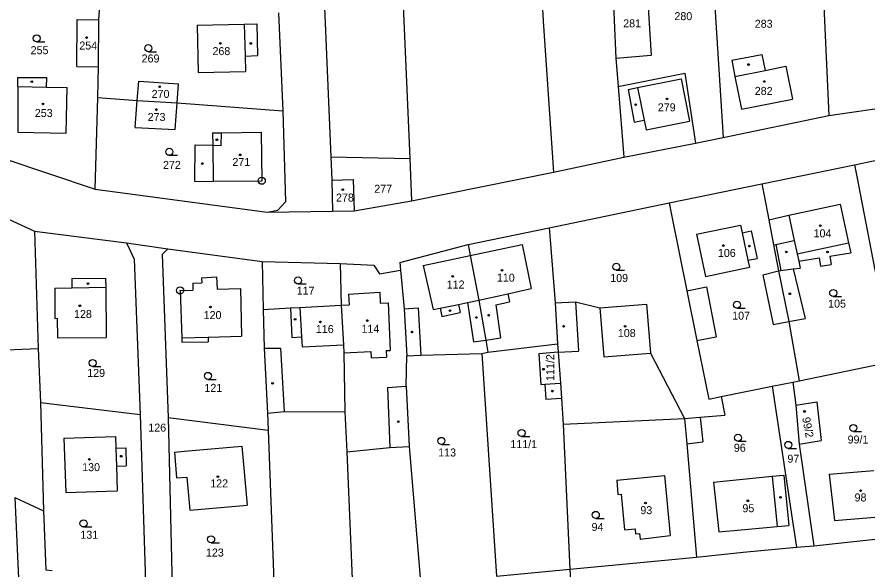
# Model space of a CAD drawing. Extents: x -779596 to -776743, y -1030330 to -1024513.
# Drawn here: x -778366.4 to -778185.6, y -1024921.7 to -1024804.1 of the extents above; entities that cross this region are included whole.
import ezdxf

# ---------------------------------------------------------------- set-up
doc = ezdxf.new("R2010")
doc.units = 0
for name, color, linetype in [('hranice parcel', 7, 'Continuous'), ('hranice vnitřní', 7, 'Continuous'), ('kultura', 7, 'Continuous'), ('Kód', 7, 'Continuous'), ('č_pacel stav_', 7, 'Continuous'), ('č_parcel poz_', 7, 'Continuous')]:
    doc.layers.add(name, color=color, linetype=linetype)

msp = doc.modelspace()

# ---------------------------------------------------------------- linework, layer by layer
at = {"layer": 'hranice parcel'}
for points in [[(-778256.34, -1024772.55), (-778254.57, -1024805)], [(-778301.94, -1024780.27), (-778299.71, -1024833.83)], [(-778218.94, -1024788.46), (-778216.34, -1024829.72)], [(-778195.58, -1024787.78), (-778193.9, -1024825.06)], [(-778232.64, -1024796.31), (-778231.66, -1024812.23)], [(-778239.85, -1024796.61), (-778239.11, -1024812.84)], [(-778348.96, -1024804.66), (-778348.79, -1024801.64)], [(-778284.34, -1024801.62), (-778282.93, -1024834.15)], [(-778310.82, -1024803.21), (-778309.88, -1024824.04)], [(-778353.64, -1024814.62), (-778353.56, -1024804.62)], [(-778353.56, -1024804.62), (-778348.96, -1024804.66)], [(-778349.04, -1024814.66), (-778348.96, -1024804.66)], [(-778318.07, -1024805.6), (-778315.4, -1024805.53)], [(-778315.4, -1024805.53), (-778315.24, -1024812.3)], [(-778254.57, -1024805), (-778252.38, -1024837.07)], [(-778328.08, -1024805.83), (-778318.07, -1024805.6)], [(-778328.08, -1024805.83), (-778327.84, -1024815.89)], [(-778317.91, -1024812.38), (-778315.24, -1024812.3)], [(-778317.91, -1024812.38), (-778317.83, -1024815.66)], [(-778239.11, -1024812.84), (-778231.66, -1024812.23)], [(-778214.51, -1024813.26), (-778208.08, -1024812.08)], [(-778208.08, -1024812.08), (-778207.42, -1024815.44)], [(-778239.11, -1024812.84), (-778238.64, -1024818.89)], [(-778214.51, -1024813.26), (-778213.83, -1024816.71)], [(-778207.42, -1024815.44), (-778203, -1024814.57)], [(-778203, -1024814.57), (-778201.62, -1024821.54)], [(-778353.64, -1024814.62), (-778349.04, -1024814.66)], [(-778349.21, -1024821.2), (-778349.04, -1024814.66)], [(-778327.84, -1024815.89), (-778317.83, -1024815.66)], [(-778238.64, -1024818.89), (-778224.49, -1024816.06)], [(-778224.49, -1024816.06), (-778222.21, -1024830.88)], [(-778366.2, -1024816.96), (-778360.04, -1024816.97)], [(-778366.2, -1024818.85), (-778366.2, -1024816.96)], [(-778360.08, -1024818.97), (-778360.04, -1024816.97)], [(-778340.81, -1024821.87), (-778340.49, -1024817.73)], [(-778340.49, -1024817.73), (-778332.08, -1024818.33)], [(-778213.83, -1024816.71), (-778212.45, -1024823.68)], [(-778366.2, -1024818.85), (-778366.18, -1024828.6)], [(-778360.08, -1024818.97), (-778355.73, -1024819.06)], [(-778355.92, -1024828.8), (-778355.73, -1024819.06)], [(-778332.33, -1024822.31), (-778332.08, -1024818.33)], [(-778238.64, -1024818.89), (-778237.46, -1024833.89)], [(-778349.75, -1024840.68), (-778349.21, -1024821.2)], [(-778349.21, -1024821.2), (-778340.81, -1024821.87)], [(-778212.45, -1024823.68), (-778201.62, -1024821.54)], [(-778341.28, -1024827.57), (-778340.81, -1024821.87)], [(-778340.81, -1024821.87), (-778332.33, -1024822.31)], [(-778332.78, -1024828), (-778332.33, -1024822.31)], [(-778332.33, -1024822.31), (-778309.88, -1024824.04)], [(-778193.9, -1024825.06), (-778184.1, -1024823.61)], [(-778309.88, -1024824.04), (-778309.34, -1024843.4)], [(-778216.34, -1024829.72), (-778193.9, -1024825.06)], [(-778366.18, -1024828.6), (-778355.92, -1024828.8)], [(-778341.28, -1024827.57), (-778332.78, -1024828)], [(-778324.8, -1024828.71), (-778322.91, -1024828.69)], [(-778324.8, -1024828.71), (-778324.77, -1024831.35)], [(-778322.91, -1024828.69), (-778314.47, -1024828.6)], [(-778314.47, -1024828.6), (-778314.37, -1024838.91)], [(-778222.21, -1024830.88), (-778216.34, -1024829.72)], [(-778328.6, -1024839.03), (-778328.49, -1024831.24)], [(-778328.49, -1024831.24), (-778324.77, -1024831.35)], [(-778237.46, -1024833.89), (-778222.21, -1024830.88)], [(-778188.42, -1024835.49), (-778173.59, -1024832.42)], [(-778369.19, -1024834.14), (-778349.75, -1024840.68)], [(-778299.71, -1024833.83), (-778282.93, -1024834.15)], [(-778299.71, -1024833.83), (-778299.46, -1024838.75)], [(-778282.93, -1024834.15), (-778282.54, -1024843.14)], [(-778252.38, -1024837.07), (-778237.46, -1024833.89)], [(-778208.13, -1024839.56), (-778188.42, -1024835.49)], [(-778188.42, -1024835.49), (-778187.93, -1024838.01)], [(-778282.54, -1024843.14), (-778252.38, -1024837.07)], [(-778187.93, -1024838.01), (-778180.36, -1024877.36)], [(-778328.6, -1024839.03), (-778324.69, -1024839)], [(-778324.69, -1024839), (-778314.37, -1024838.91)], [(-778299.46, -1024838.75), (-778294.92, -1024838.64)], [(-778299.46, -1024838.75), (-778299.31, -1024845.38)], [(-778294.92, -1024838.64), (-778294.76, -1024845.28)], [(-778227.83, -1024843.63), (-778208.13, -1024839.56)], [(-778208.13, -1024839.56), (-778207.65, -1024842.05)], [(-778380.51, -1024841.39), (-778362.66, -1024849.65)], [(-778349.75, -1024840.68), (-778313.18, -1024845.6)], [(-778310.98, -1024845.12), (-778309.34, -1024843.4)], [(-778294.76, -1024845.28), (-778282.54, -1024843.14)], [(-778207.65, -1024842.05), (-778206.66, -1024847.18)], [(-778313.18, -1024845.6), (-778310.98, -1024845.12)], [(-778299.31, -1024845.38), (-778294.76, -1024845.28)], [(-778253.29, -1024848.88), (-778227.83, -1024843.63)], [(-778227.83, -1024843.63), (-778227.32, -1024846.16)], [(-778202.36, -1024846.25), (-778191.48, -1024843.89)], [(-778191.48, -1024843.89), (-778189.67, -1024852.09)], [(-778313.18, -1024845.6), (-778299.31, -1024845.38)], [(-778227.32, -1024846.16), (-778224.02, -1024862.29)], [(-778206.66, -1024847.18), (-778202.36, -1024846.25)], [(-778270.52, -1024852.44), (-778253.29, -1024848.88)], [(-778253.29, -1024848.88), (-778253.08, -1024851.45)], [(-778221.99, -1024850.28), (-778212.66, -1024848.32)], [(-778212.66, -1024848.32), (-778212.31, -1024849.95)], [(-778206.66, -1024847.18), (-778205.62, -1024852.53)], [(-778362.66, -1024849.65), (-778343.1, -1024852.11)], [(-778362.66, -1024849.65), (-778361.84, -1024874.54)], [(-778221.99, -1024850.28), (-778220.1, -1024859.27)], [(-778212.31, -1024849.95), (-778210.36, -1024849.54)], [(-778210.36, -1024849.54), (-778209.12, -1024855.4)], [(-778343.1, -1024852.11), (-778334.33, -1024853.38)], [(-778343.1, -1024852.11), (-778341.49, -1024855.59)], [(-778285.04, -1024856.31), (-778270.52, -1024852.44)], [(-778270.52, -1024852.44), (-778270.06, -1024854.8)], [(-778253.08, -1024851.45), (-778252.01, -1024864.87)], [(-778205.62, -1024852.53), (-778204.55, -1024858.06)], [(-778189.67, -1024852.09), (-778189.2, -1024854.2)], [(-778335.53, -1024854.58), (-778334.33, -1024853.38)], [(-778334.33, -1024853.38), (-778314.27, -1024856.1)], [(-778193.64, -1024854.94), (-778189.2, -1024854.2)], [(-778341.49, -1024855.59), (-778340.22, -1024888.58)], [(-778335.53, -1024854.58), (-778334.26, -1024889.22)], [(-778314.27, -1024856.1), (-778314.05, -1024866.26)], [(-778314.27, -1024856.1), (-778297.73, -1024856.46)], [(-778270.06, -1024854.8), (-778268.22, -1024864.3)], [(-778211.06, -1024855.81), (-778209.12, -1024855.4)], [(-778211.06, -1024855.81), (-778210.75, -1024857.3)], [(-778200.25, -1024856.03), (-778195.92, -1024855.31)], [(-778200.25, -1024856.03), (-778199.94, -1024857.46)], [(-778195.92, -1024855.31), (-778195.63, -1024857.07)], [(-778193.64, -1024854.94), (-778193.36, -1024856.69)], [(-778297.73, -1024856.46), (-778290.52, -1024856.86)], [(-778297.73, -1024856.46), (-778297.46, -1024865.37)], [(-778290.52, -1024856.86), (-778289.36, -1024858.7)], [(-778289.36, -1024858.7), (-778284.92, -1024857.9)], [(-778285.04, -1024856.31), (-778284.92, -1024857.9)], [(-778284.92, -1024857.9), (-778284.11, -1024866.13)], [(-778220.1, -1024859.27), (-778210.75, -1024857.3)], [(-778201.49, -1024857.66), (-778199.94, -1024857.46)], [(-778201.49, -1024857.66), (-778198.91, -1024868.18)], [(-778195.63, -1024857.07), (-778193.36, -1024856.69)], [(-778354.73, -1024859.68), (-778347.53, -1024859.61)], [(-778354.73, -1024859.68), (-778354.71, -1024861.69)], [(-778347.53, -1024859.61), (-778347.51, -1024861.55)], [(-778327.16, -1024859.53), (-778323.95, -1024859.36)], [(-778327.16, -1024859.53), (-778327.13, -1024860.6)], [(-778323.95, -1024859.36), (-778323.87, -1024861.97)], [(-778204.55, -1024858.06), (-778202.35, -1024868.81)], [(-778347.51, -1024861.55), (-778347.4, -1024872.19)], [(-778329.04, -1024860.66), (-778327.13, -1024860.6)], [(-778329.04, -1024860.66), (-778328.99, -1024862.13)], [(-778358.36, -1024861.73), (-778354.71, -1024861.69)], [(-778358.36, -1024861.73), (-778358.3, -1024868.15)], [(-778331.7, -1024862.22), (-778328.99, -1024862.13)], [(-778331.7, -1024862.22), (-778331.37, -1024872.27)], [(-778323.87, -1024861.97), (-778318.91, -1024861.81)], [(-778318.91, -1024861.81), (-778318.65, -1024871.95)], [(-778224.02, -1024862.29), (-778221.95, -1024872.89)], [(-778268.22, -1024864.3), (-778266.77, -1024872.76)], [(-778252.01, -1024864.87), (-778247.73, -1024864.61)], [(-778252.01, -1024864.87), (-778251.53, -1024873.56)], [(-778247.73, -1024864.61), (-778242.56, -1024865.95)], [(-778242.56, -1024865.95), (-778232.63, -1024865.14)], [(-778232.63, -1024865.14), (-778231.78, -1024875.52)], [(-778314.05, -1024866.26), (-778308.29, -1024865.95)], [(-778314.05, -1024866.26), (-778313.87, -1024874.52)], [(-778308.29, -1024865.95), (-778306.24, -1024865.84)], [(-778306.24, -1024865.84), (-778297.46, -1024865.37)], [(-778297.46, -1024865.37), (-778297.01, -1024873.76)], [(-778284.11, -1024866.13), (-778283.54, -1024876.13)], [(-778358.3, -1024868.15), (-778357.83, -1024868.14)], [(-778357.83, -1024868.14), (-778357.78, -1024872.3)], [(-778202.35, -1024868.81), (-778198.91, -1024868.18)], [(-778202.35, -1024868.81), (-778200.17, -1024881.44)], [(-778357.78, -1024872.3), (-778347.4, -1024872.19)], [(-778331.37, -1024872.27), (-778331.35, -1024873.21)], [(-778325.77, -1024872.13), (-778318.65, -1024871.95)], [(-778325.77, -1024872.13), (-778325.75, -1024873.13)], [(-778331.35, -1024873.21), (-778325.75, -1024873.13)], [(-778297.01, -1024873.76), (-778296.92, -1024875.45)], [(-778266.77, -1024872.76), (-778266.32, -1024875.36)], [(-778266.32, -1024875.36), (-778251.53, -1024873.56)], [(-778251.53, -1024873.56), (-778251.36, -1024875.37)], [(-778221.95, -1024872.89), (-778219.39, -1024885.31)], [(-778382.36, -1024875.42), (-778361.84, -1024874.54)], [(-778361.84, -1024874.54), (-778361.4, -1024886.04)], [(-778313.87, -1024874.52), (-778313.13, -1024888.28)], [(-778296.92, -1024875.45), (-778296.68, -1024888.03)], [(-778283.54, -1024876.13), (-778280.56, -1024875.95)], [(-778280.56, -1024875.95), (-778267.62, -1024875.64)], [(-778267.62, -1024875.64), (-778266.32, -1024875.36)], [(-778267.62, -1024875.64), (-778264.46, -1024922.95)], [(-778251.36, -1024875.37), (-778255.52, -1024875.69), (-778255.1, -1024882.24), (-778254.2, -1024882.18)], [(-778251.36, -1024875.37), (-778250.91, -1024881.94)], [(-778231.78, -1024875.52), (-778224.52, -1024889.41)], [(-778283.65, -1024882.57), (-778283.54, -1024876.13)], [(-778200.17, -1024881.44), (-778180.36, -1024877.36)], [(-778201.55, -1024881.73), (-778200.17, -1024881.44)], [(-778283.65, -1024882.57), (-778283.04, -1024895.41)], [(-778254.2, -1024882.18), (-778253.99, -1024885.35), (-778250.7, -1024885.11)], [(-778250.91, -1024881.94), (-778250.7, -1024885.11)], [(-778216.75, -1024884.78), (-778205.89, -1024882.6)], [(-778205.89, -1024882.6), (-778201.55, -1024881.73)], [(-778205.89, -1024882.6), (-778201.45, -1024912.17)], [(-778201.55, -1024881.73), (-778200.92, -1024886.61)], [(-778219.39, -1024885.31), (-778216.75, -1024884.78)], [(-778216.75, -1024884.78), (-778215.95, -1024888.76)], [(-778361.4, -1024886.04), (-778360.72, -1024909.04)], [(-778361.4, -1024886.04), (-778340.22, -1024888.58)], [(-778250.7, -1024885.11), (-778250.32, -1024890.66)], [(-778200.92, -1024886.61), (-778196.42, -1024885.87)], [(-778200.92, -1024886.61), (-778200.15, -1024894.89)], [(-778196.42, -1024885.87), (-778195.49, -1024894.14)], [(-778340.22, -1024888.58), (-778339.08, -1024924.32)], [(-778313.13, -1024888.28), (-778309.63, -1024887.94)], [(-778313.13, -1024888.28), (-778312.99, -1024891.95)], [(-778309.63, -1024887.94), (-778296.68, -1024888.03)], [(-778296.68, -1024888.03), (-778296.32, -1024896.54)], [(-778334.26, -1024889.22), (-778333.42, -1024925.33)], [(-778334.26, -1024889.22), (-778312.99, -1024891.95)], [(-778250.32, -1024890.66), (-778224.52, -1024889.41)], [(-778224.52, -1024889.41), (-778221.19, -1024889.16)], [(-778224.52, -1024889.41), (-778224.05, -1024894.82)], [(-778221.19, -1024889.16), (-778215.95, -1024888.76)], [(-778312.99, -1024891.95), (-778311.64, -1024927.84)], [(-778250.32, -1024890.66), (-778248.92, -1024921.44)], [(-778356.4, -1024893.65), (-778345.45, -1024893.28)], [(-778356.4, -1024893.65), (-778356.01, -1024905.17)], [(-778345.45, -1024893.28), (-778345.37, -1024895.77)], [(-778345.37, -1024895.77), (-778343.27, -1024895.69)], [(-778343.27, -1024895.69), (-778343.14, -1024899.5)], [(-778330.76, -1024896.4), (-778318.59, -1024895.3)], [(-778318.59, -1024895.3), (-778317.47, -1024907.85)], [(-778296.32, -1024896.54), (-778287.13, -1024895.63)], [(-778287.13, -1024895.63), (-778283.04, -1024895.41)], [(-778283.04, -1024895.41), (-778278.99, -1024943.52)], [(-778224.05, -1024894.82), (-778221.99, -1024918.91)], [(-778200.15, -1024894.89), (-778195.49, -1024894.14)], [(-778200.15, -1024894.89), (-778197.06, -1024916.48)], [(-778332.9, -1024896.59), (-778330.76, -1024896.4)], [(-778332.9, -1024896.59), (-778332.47, -1024902.09)], [(-778296.32, -1024896.54), (-778294.27, -1024943.79)], [(-778345.24, -1024899.57), (-778343.14, -1024899.5)], [(-778345.24, -1024899.57), (-778345.07, -1024904.8)], [(-778193.8, -1024901.26), (-778184.29, -1024900.49)], [(-778193.8, -1024901.26), (-778192.67, -1024911.14)], [(-778332.47, -1024902.09), (-778330.26, -1024901.9)], [(-778330.26, -1024901.9), (-778329.63, -1024908.95)], [(-778238.94, -1024902.55), (-778228.82, -1024901.59)], [(-778238.94, -1024902.55), (-778238.7, -1024905.6)], [(-778228.82, -1024901.59), (-778227.62, -1024914.32)], [(-778218.38, -1024902.95), (-778205.9, -1024901.73)], [(-778218.38, -1024902.95), (-778217.25, -1024913.55)], [(-778205.9, -1024901.73), (-778203.42, -1024901.49)], [(-778203.42, -1024901.49), (-778202.4, -1024912.18)], [(-778356.01, -1024905.17), (-778345.07, -1024904.8)], [(-778366.82, -1024906.22), (-778360.72, -1024909.04)], [(-778366.82, -1024906.22), (-778364.24, -1024963.97)], [(-778238.7, -1024905.6), (-778237.97, -1024905.56)], [(-778237.97, -1024905.56), (-778237.26, -1024913.1)], [(-778329.63, -1024908.95), (-778317.47, -1024907.85)], [(-778360.72, -1024909.04), (-778360.27, -1024921.6)], [(-778192.67, -1024911.14), (-778180.62, -1024910.17)], [(-778204.85, -1024912.41), (-778202.4, -1024912.18)], [(-778201.45, -1024912.17), (-778200.75, -1024916.82)], [(-778237.26, -1024913.1), (-778235.06, -1024912.88)], [(-778235.06, -1024912.88), (-778234.96, -1024913.93)], [(-778234.96, -1024913.93), (-778234.08, -1024913.87)], [(-778234.08, -1024913.87), (-778233.97, -1024915.08)], [(-778217.25, -1024913.55), (-778212.49, -1024913.11)], [(-778212.49, -1024913.11), (-778204.85, -1024912.41)], [(-778233.97, -1024915.08), (-778227.62, -1024914.32)], [(-778197.06, -1024916.48), (-778174.88, -1024914.1)], [(-778212.09, -1024917.86), (-778200.75, -1024916.82)], [(-778200.75, -1024916.82), (-778197.06, -1024916.48)], [(-778248.92, -1024921.44), (-778221.99, -1024918.91)], [(-778221.99, -1024918.91), (-778216.74, -1024918.35)], [(-778216.74, -1024918.35), (-778212.09, -1024917.86)], [(-778360.27, -1024921.6), (-778358.88, -1024921.78)], [(-778264.46, -1024922.95), (-778248.92, -1024921.44)], [(-778248.92, -1024921.44), (-778248.34, -1024931.1)]]:
    msp.add_lwpolyline(points, dxfattribs=at)
at = {"layer": 'hranice vnitřní'}
for points in [[(-778318.07, -1024805.6), (-778317.91, -1024812.38)], [(-778213.83, -1024816.71), (-778207.42, -1024815.44)], [(-778234.51, -1024819.08), (-778225.27, -1024817.23)], [(-778225.27, -1024817.23), (-778223.47, -1024826.2)], [(-778366.2, -1024818.85), (-778360.08, -1024818.97)], [(-778236.53, -1024819.48), (-778234.51, -1024819.08)], [(-778236.53, -1024819.48), (-778235.27, -1024826.46)], [(-778234.51, -1024819.08), (-778233.12, -1024826.03)], [(-778235.27, -1024826.46), (-778233.12, -1024826.03)], [(-778233.12, -1024826.03), (-778232.71, -1024828.05)], [(-778232.71, -1024828.05), (-778223.47, -1024826.2)], [(-778322.98, -1024831.4), (-778322.91, -1024828.69)], [(-778324.77, -1024831.35), (-778322.98, -1024831.4)], [(-778324.77, -1024831.35), (-778324.69, -1024839)], [(-778202.36, -1024846.25), (-778201.21, -1024851.58)], [(-778212.31, -1024849.95), (-778211.06, -1024855.81)], [(-778270.06, -1024854.8), (-778259.05, -1024852.48)], [(-778259.05, -1024852.48), (-778257.09, -1024861.82)], [(-778205.62, -1024852.53), (-778205.12, -1024852.42)], [(-778205.12, -1024852.42), (-778201.21, -1024851.58)], [(-778205.12, -1024852.42), (-778204.05, -1024858)], [(-778201.21, -1024851.58), (-778200.59, -1024854.46)], [(-778200.59, -1024854.46), (-778189.67, -1024852.09)], [(-778280.09, -1024856.9), (-778270.06, -1024854.8)], [(-778200.59, -1024854.46), (-778200.25, -1024856.03)], [(-778280.09, -1024856.9), (-778277.93, -1024866.28)], [(-778204.05, -1024858), (-778201.49, -1024857.66)], [(-778207.89, -1024858.91), (-778204.55, -1024858.06)], [(-778207.89, -1024858.91), (-778205.71, -1024869.43)], [(-778204.55, -1024858.06), (-778204.05, -1024858)], [(-778354.71, -1024861.69), (-778347.51, -1024861.55)], [(-778224.02, -1024862.29), (-778219.9, -1024861.48)], [(-778219.9, -1024861.48), (-778217.83, -1024872.08)], [(-778295.93, -1024863.02), (-778289.31, -1024862.61)], [(-778295.93, -1024863.02), (-778295.81, -1024865.28)], [(-778289.31, -1024862.61), (-778289.18, -1024864.93)], [(-778268.22, -1024864.3), (-778262.1, -1024862.93)], [(-778262.1, -1024862.93), (-778257.09, -1024861.82)], [(-778262.1, -1024862.93), (-778261.72, -1024864.63)], [(-778289.18, -1024864.93), (-778287.49, -1024864.84)], [(-778287.49, -1024864.84), (-778287.08, -1024874.97)], [(-778276.46, -1024865.98), (-778272.54, -1024865.18)], [(-778272.54, -1024865.18), (-778270.62, -1024864.79)], [(-778272.54, -1024865.18), (-778272.19, -1024866.94)], [(-778270.62, -1024864.79), (-778268.22, -1024864.3)], [(-778270.62, -1024864.79), (-778269.39, -1024873.15)], [(-778264.65, -1024865.28), (-778261.72, -1024864.63)], [(-778247.73, -1024864.61), (-778247.08, -1024875.11)], [(-778308.29, -1024865.95), (-778307.94, -1024872.22)], [(-778306.24, -1024865.84), (-778305.9, -1024872.11)], [(-778297.46, -1024865.37), (-778295.81, -1024865.28)], [(-778284.11, -1024866.13), (-778281.13, -1024865.95)], [(-778281.13, -1024865.95), (-778280.56, -1024875.95)], [(-778277.93, -1024866.28), (-778276.46, -1024865.98)], [(-778276.46, -1024865.98), (-778276.11, -1024867.73)], [(-778276.11, -1024867.73), (-778272.19, -1024866.94)], [(-778264.65, -1024865.28), (-778263.65, -1024872.31)], [(-778242.56, -1024865.95), (-778241.71, -1024876.33)], [(-778205.71, -1024869.43), (-778202.35, -1024868.81)], [(-778331.37, -1024872.27), (-778325.77, -1024872.13)], [(-778307.94, -1024872.22), (-778305.9, -1024872.11)], [(-778305.9, -1024872.11), (-778305.79, -1024874.23)], [(-778266.77, -1024872.76), (-778263.65, -1024872.31)], [(-778221.95, -1024872.89), (-778217.83, -1024872.08)], [(-778305.79, -1024874.23), (-778297.01, -1024873.76)], [(-778269.39, -1024873.15), (-778266.77, -1024872.76)], [(-778313.87, -1024874.52), (-778310.41, -1024874.48)], [(-778310.41, -1024874.48), (-778309.63, -1024887.94)], [(-778296.92, -1024875.45), (-778291.16, -1024875.17)], [(-778291.16, -1024875.17), (-778291.1, -1024876.53)], [(-778287.93, -1024875.01), (-778287.08, -1024874.97)], [(-778287.93, -1024875.01), (-778287.86, -1024876.37)], [(-778251.36, -1024875.37), (-778247.08, -1024875.11)], [(-778241.71, -1024876.33), (-778231.78, -1024875.52)], [(-778291.1, -1024876.53), (-778287.86, -1024876.37)], [(-778287.67, -1024882.86), (-778283.65, -1024882.57)], [(-778287.67, -1024882.86), (-778287.13, -1024895.63)], [(-778254.2, -1024882.18), (-778250.91, -1024881.94)], [(-778221.19, -1024889.16), (-778220.65, -1024894.39)], [(-778345.37, -1024895.77), (-778345.24, -1024899.57)], [(-778224.05, -1024894.82), (-778220.65, -1024894.39)], [(-778205.9, -1024901.73), (-778204.85, -1024912.41)]]:
    msp.add_lwpolyline(points, dxfattribs=at)
at = {"layer": 'kultura'}
for points in [[(-778362.19, -1024809.38), (-778360.44, -1024809.38)], [(-778338.45, -1024811.46), (-778336.7, -1024811.46)], [(-778334, -1024833.49), (-778332.25, -1024833.49)], [(-778239.04, -1024857.93), (-778237.29, -1024857.93)], [(-778306.65, -1024860.84), (-778304.9, -1024860.84)], [(-778192.95, -1024863.52), (-778191.2, -1024863.52)], [(-778213.4, -1024866.01), (-778211.65, -1024866.01)], [(-778350.3, -1024878.4), (-778348.55, -1024878.4)], [(-778325.8, -1024881.13), (-778324.05, -1024881.13)], [(-778188.67, -1024892.2), (-778186.92, -1024892.2)], [(-778259.16, -1024893.27), (-778257.41, -1024893.27)], [(-778276.2, -1024894.95), (-778274.45, -1024894.95)], [(-778213.18, -1024894.28), (-778211.43, -1024894.28)], [(-778202.5, -1024895.8), (-778200.75, -1024895.8)], [(-778243.39, -1024910.69), (-778241.64, -1024910.69)], [(-778352.23, -1024912.51), (-778350.48, -1024912.51)], [(-778325.12, -1024915.87), (-778323.37, -1024915.87)]]:
    msp.add_lwpolyline(points, dxfattribs=at)
for centre, radius in [((-778362.19, -1024808.63), 0.75), ((-778351.58, -1024808.46), 0.175), ((-778338.45, -1024810.71), 0.75), ((-778323.18, -1024809.71), 0.175), ((-778316.69, -1024809.71), 0.175), ((-778210.93, -1024814.2), 0.175), ((-778363.22, -1024817.84), 0.175), ((-778207.6, -1024817.8), 0.175), ((-778336.04, -1024818.93), 0.175), ((-778228.28, -1024821.5), 0.175), ((-778360.85, -1024822.58), 0.175), ((-778336.75, -1024823.77), 0.175), ((-778234.93, -1024822.74), 0.175), ((-778323.9, -1024830.19), 0.175), ((-778334, -1024832.74), 0.75), ((-778318.95, -1024833.39), 0.175), ((-778326.99, -1024835.24), 0.175), ((-778297.14, -1024840.78), 0.175), ((-778195.7, -1024848.44), 0.175), ((-778216.3, -1024852.67), 0.175), ((-778210.78, -1024852.8), 0.175), ((-778202.91, -1024854.03), 0.175), ((-778194.15, -1024854.03), 0.175), ((-778263.33, -1024857.92), 0.175), ((-778239.04, -1024857.18), 0.75), ((-778306.65, -1024860.09), 0.75), ((-778273.79, -1024859.23), 0.175), ((-778351.27, -1024860.76), 0.175), ((-778202.17, -1024862.93), 0.175), ((-778192.95, -1024862.77), 0.75), ((-778213.4, -1024865.26), 0.75), ((-778353, -1024865.48), 0.175), ((-778325.26, -1024865.74), 0.175), ((-778274.37, -1024866.52), 0.175), ((-778307.28, -1024868.37), 0.175), ((-778301.9, -1024868.91), 0.175), ((-778291.93, -1024868.62), 0.175), ((-778268.79, -1024867.97), 0.175), ((-778266.16, -1024867.49), 0.175), ((-778250.23, -1024869.84), 0.175), ((-778237.16, -1024869.84), 0.175), ((-778282.43, -1024871.06), 0.175), ((-778350.3, -1024877.65), 0.75), ((-778325.8, -1024880.38), 0.75), ((-778254.51, -1024878.96), 0.175), ((-778312.07, -1024881.95), 0.175), ((-778252.63, -1024883.63), 0.175), ((-778199.05, -1024887.95), 0.175), ((-778285.36, -1024890.13), 0.175), ((-778259.16, -1024892.52), 0.75), ((-778188.67, -1024891.45), 0.75), ((-778276.2, -1024894.2), 0.75), ((-778213.18, -1024893.53), 0.75), ((-778202.5, -1024895.05), 0.75), ((-778344.23, -1024897.46), 0.175), ((-778350.98, -1024898.14), 0.175), ((-778323.69, -1024901.81), 0.175), ((-778187.13, -1024904.79), 0.175), ((-778211.09, -1024906.94), 0.175), ((-778204.15, -1024906.2), 0.175), ((-778232.84, -1024907.41), 0.175), ((-778243.39, -1024909.94), 0.75), ((-778352.23, -1024911.76), 0.75), ((-778325.12, -1024915.12), 0.75)]:
    msp.add_circle(centre, radius, dxfattribs=at)
at = {"layer": 'Kód'}
for centre, radius in [((-778314.36, -1024838.91), 0.75), ((-778314.36, -1024838.91), 0.032), ((-778331.7, -1024862.22), 0.75), ((-778331.7, -1024862.22), 0.032)]:
    msp.add_circle(centre, radius, dxfattribs=at)

# ---------------------------------------------------------------- texts
at = {"layer": 'č_pacel stav_'}
for s, p in [('281', (-778237.57, -1024806.29)), ('254', (-778353.13, -1024811)), ('268', (-778324.84, -1024812.19)), ('270', (-778337.76, -1024821.29)), ('282', (-778209.62, -1024820.65)), ('253', (-778362.58, -1024825.34)), ('279', (-778230.22, -1024824.14)), ('273', (-778338.61, -1024826.2)), ('271', (-778320.61, -1024835.76)), ('278', (-778298.59, -1024843.32)), ('104', (-778197.12, -1024850.93)), ('106', (-778217.45, -1024855.1)), ('110', (-778264.41, -1024860.35)), ('112', (-778275.07, -1024861.81)), ('128', (-778354.25, -1024868.08)), ('120', (-778326.71, -1024868.3)), ('116', (-778302.87, -1024871.27)), ('114', (-778293.17, -1024871.21)), ('108', (-778238.71, -1024872.13)), ('130', (-778352.52, -1024900.64)), ('122', (-778325.31, -1024904.09)), ('98', (-778188.41, -1024907.08)), ('93', (-778233.92, -1024909.78)), ('95', (-778212.24, -1024909.37))]:
    msp.add_text(s, height=1.7, dxfattribs=at).set_placement(p)
for s, rotation, p in [('111/2', 90.00072, (-778252.23, -1024881.452)), ('99/2', 280.70223, (-778199.557, -1024889.319))]:
    msp.add_text(s, height=1.7, rotation=rotation, dxfattribs=at).set_placement(p)
at = {"layer": 'č_parcel poz_'}
for s, p in [('280', (-778226.69, -1024804.76)), ('283', (-778209.62, -1024806.38)), ('255', (-778363.47, -1024811.99)), ('269', (-778339.89, -1024813.75)), ('272', (-778335.35, -1024836.38)), ('277', (-778290.46, -1024841.45)), ('109', (-778240.33, -1024860.42)), ('117', (-778306.94, -1024863.12)), ('105', (-778194.03, -1024865.88)), ('107', (-778214.42, -1024868.44)), ('129', (-778351.45, -1024880.61)), ('121', (-778326.55, -1024883.78)), ('126', (-778338.47, -1024892.23)), ('111/1', (-778261.553, -1024895.75)), ('99/1', (-778189.89, -1024894.76)), ('113', (-778276.88, -1024897.52)), ('96', (-778214.06, -1024896.51)), ('97', (-778202.68, -1024898.84)), ('94', (-778244.29, -1024913.35)), ('131', (-778352.9, -1024915.01)), ('123', (-778326.22, -1024918.79))]:
    msp.add_text(s, height=1.7, dxfattribs=at).set_placement(p)

doc.saveas('drawing.dxf')
